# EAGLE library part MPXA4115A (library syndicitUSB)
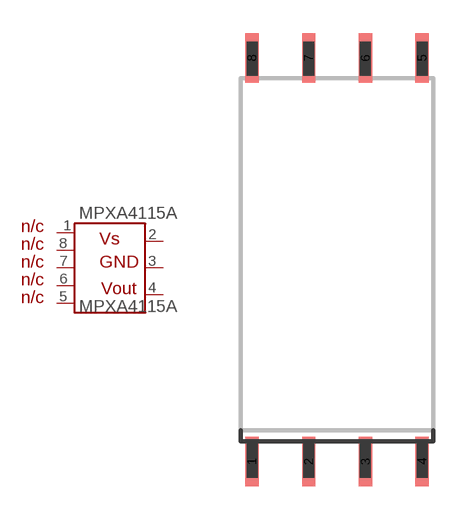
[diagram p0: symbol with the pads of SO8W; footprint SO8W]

Designator prefix MPXA4115A

## MPXA4115A  [SO8W]
1  1  pas
2  2  pas
3  3  pas
4  4  pas
5  5  pas
6  6  pas
7  7  pas
8  8  pas

## Footprint SO8W (pad centres in mm)
smd 0.6 x 2.2: 1 -3.175,-4.6; 2 -0.635,-4.6; 3 1.905,-4.6; 4 4.445,-4.6; 5 4.445,13.49; 6 1.905,13.49; 7 -0.635,13.49; 8 -3.175,13.49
